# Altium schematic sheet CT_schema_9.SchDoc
size 308 x 210 mm
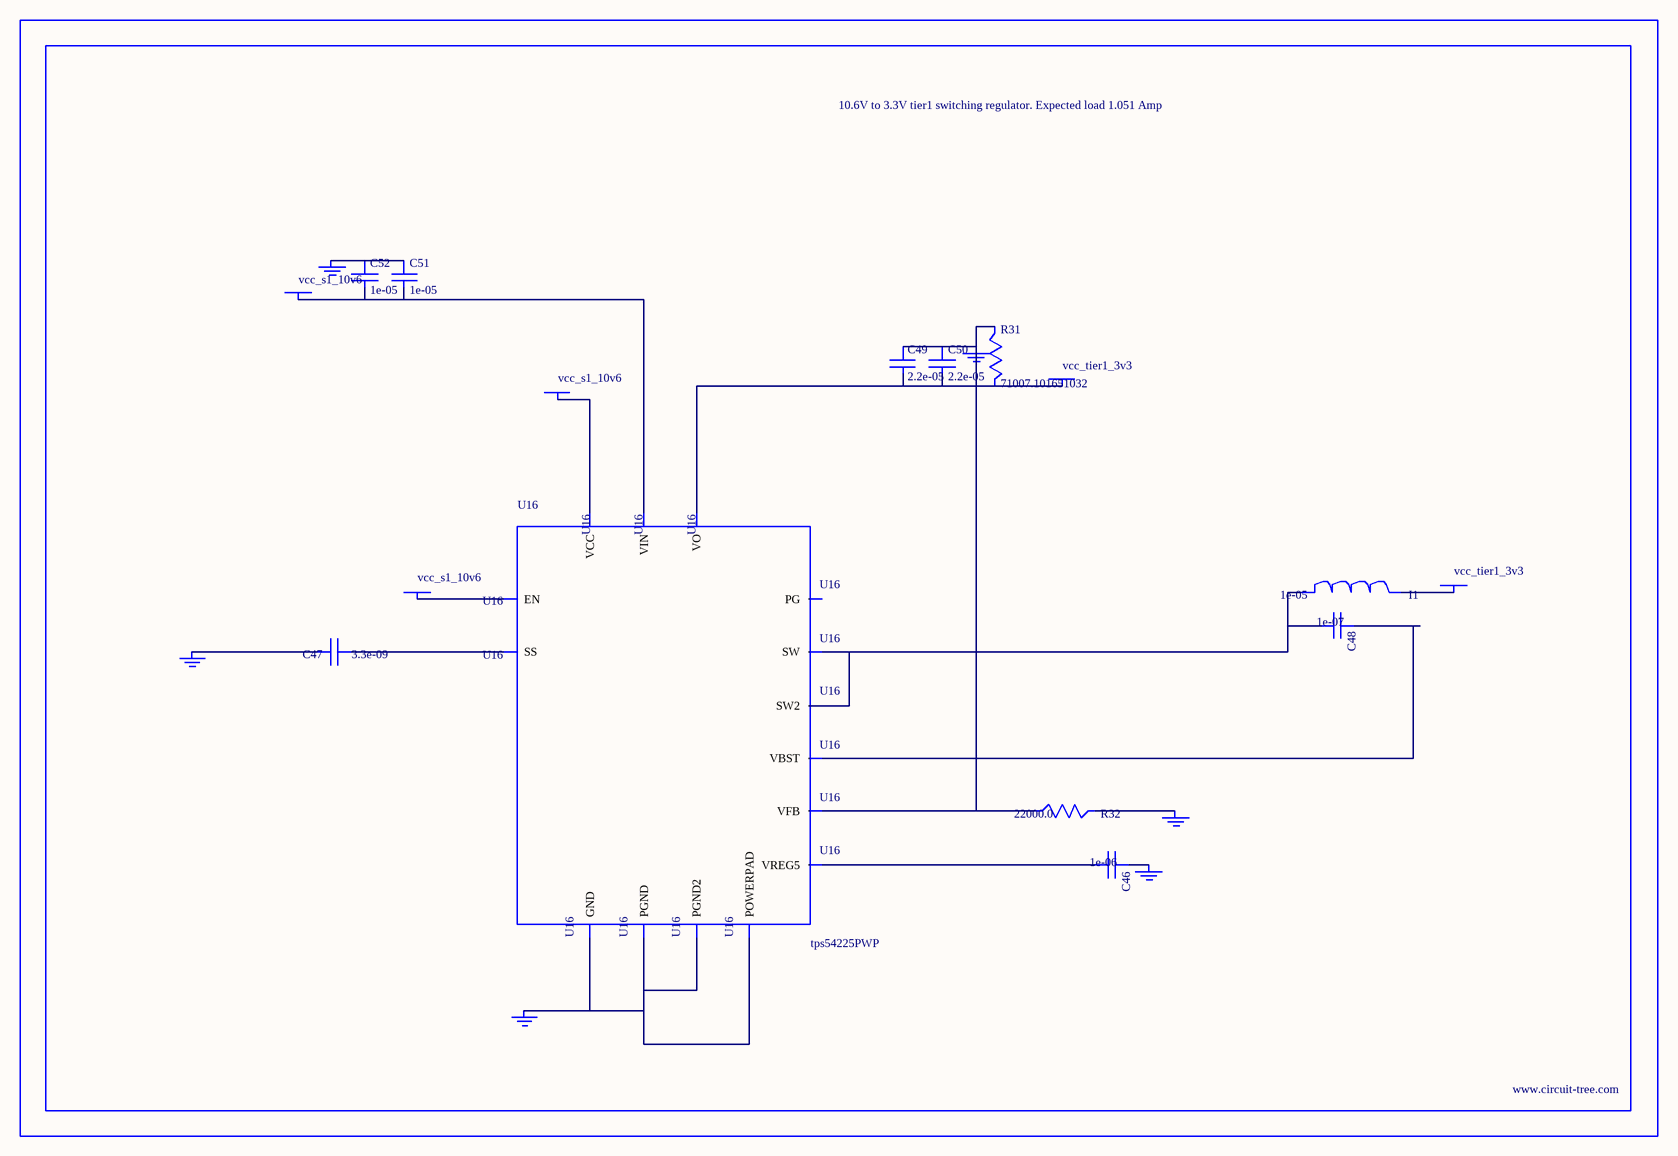
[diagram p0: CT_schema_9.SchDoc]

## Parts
BORDER8  (no value)
C46  1e-06  [C0603]
C47  3.3e-09  [C0402]
C48  1e-07  [C0402]
C49  2.2e-05  [C1210]
C50  2.2e-05  [C1210]
C51  1e-05  [C1206]
C52  1e-05  [C1206]
GND_INSTANCE_8_0  (no value)
GND_INSTANCE_8_1  (no value)
GND_INSTANCE_8_2  (no value)
GND_INSTANCE_8_3  (no value)
GND_INSTANCE_8_4  (no value)
GND_INSTANCE_8_5  (no value)
I1  1e-05  [IND_PM3316]
POWER_INSTANCE_8_0  vcc_tier1_3v3
POWER_INSTANCE_8_1  vcc_s1_10v6
POWER_INSTANCE_8_2  vcc_tier1_3v3
POWER_INSTANCE_8_3  vcc_s1_10v6
POWER_INSTANCE_8_4  vcc_s1_10v6
R31  71007.101651032  [R0603]
R32  22000.0  [R0603]
U16  tps54225PWP  [HTSSOP14]

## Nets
NetC46_1: C46.1 GND_INSTANCE_8_2.0(GND)
NetC46_2: C46.2 U16.3(VREG5)
NetC47_1: C47.1 U16.4(SS)
NetC47_2: C47.2 GND_INSTANCE_8_3.0(GND)
NetC48_1: C48.1 U16.12(VBST)
NetC48_2: C48.2 I1.1 U16.10(SW) U16.11(SW2)
NetC49_1: C49.1 C50.1 GND_INSTANCE_8_0.0(GND) R31.1 R32.1 U16.2(VFB)
NetC49_2: C49.2 C50.2 POWER_INSTANCE_8_0.0(PWR) R31.2 U16.1(VO)
NetC51_1: C51.1 C52.1 GND_INSTANCE_8_5.0(GND)
NetC51_2: C51.2 C52.2 POWER_INSTANCE_8_3.0(PWR) U16.13(VIN)
NetGND_INSTANCE_8_1_0: GND_INSTANCE_8_1.0(GND) R32.2
NetGND_INSTANCE_8_4_0: GND_INSTANCE_8_4.0(GND) U16.5(GND) U16.8(PGND) U16.9(PGND2) U16.15(POWERPAD)
NetI1_2: I1.2 POWER_INSTANCE_8_2.0(PWR)
NetPOWER_INSTANCE_8_1_0: POWER_INSTANCE_8_1.0(PWR) U16.7(EN)
NetPOWER_INSTANCE_8_4_0: POWER_INSTANCE_8_4.0(PWR) U16.14(VCC)

Not connected (* = marked no-connect by the designer): U16 6(PG)

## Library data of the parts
BORDER8 = BORDER_PAGE8
C46 = C0603C105K3RACTU
C47 = C0402C332K3RAC
C48 = C0402C104K3RACTU
C49 C50 = GRM32ER61E226ME15L
C51 C52 = C1206C106K3RACTU
GND_INSTANCE_8_0-GND_INSTANCE_8_5 = GND
I1 = PM3316-100M-RC
POWER_INSTANCE_8_0-POWER_INSTANCE_8_4 = PWR
R31 = R31
R32 = RC0603JR-0722KL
